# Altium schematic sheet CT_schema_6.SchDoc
size 278 x 170 mm
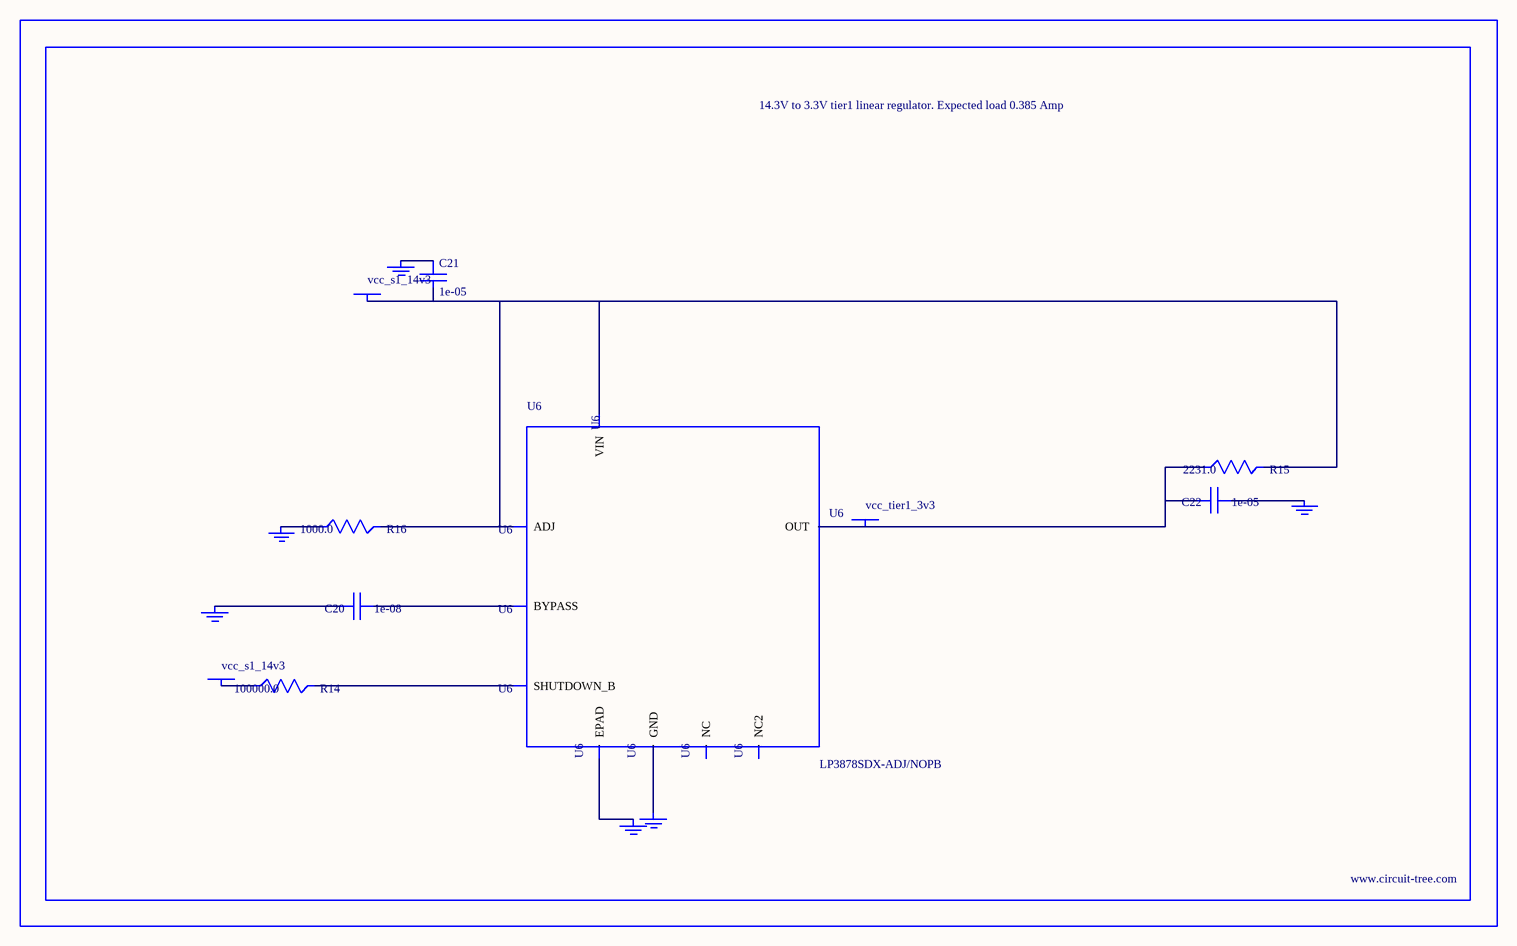
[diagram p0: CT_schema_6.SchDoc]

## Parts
BORDER5  (no value)
C20  1e-08  [C0402]
C21  1e-05  [C1210]
C22  1e-05  [C1210]
GND_INSTANCE_5_0  (no value)
GND_INSTANCE_5_1  (no value)
GND_INSTANCE_5_2  (no value)
GND_INSTANCE_5_3  (no value)
GND_INSTANCE_5_4  (no value)
GND_INSTANCE_5_5  (no value)
POWER_INSTANCE_5_0  vcc_s1_14v3
POWER_INSTANCE_5_1  vcc_s1_14v3
POWER_INSTANCE_5_2  vcc_tier1_3v3
R14  100000.0  [R0603]
R15  2231.0  [R0603]
R16  1000.0  [R0603]
U6  LP3878SDX-ADJ/NOPB  [WSON-8]

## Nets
NetC20_1: C20.1 U6.1(BYPASS)
NetC20_2: C20.2 GND_INSTANCE_5_0.0(GND)
NetC21_1: C21.1 GND_INSTANCE_5_1.0(GND)
NetC21_2: C21.2 POWER_INSTANCE_5_0.0(PWR) R15.2 R16.2 U6.4(VIN) U6.6(ADJ)
NetC22_1: C22.1 GND_INSTANCE_5_2.0(GND)
NetC22_2: C22.2 POWER_INSTANCE_5_2.0(PWR) R15.1 U6.5(OUT)
NetGND_INSTANCE_5_3_0: GND_INSTANCE_5_3.0(GND) R16.1
NetGND_INSTANCE_5_4_0: GND_INSTANCE_5_4.0(GND) U6.PAD(EPAD)
NetGND_INSTANCE_5_5_0: GND_INSTANCE_5_5.0(GND) U6.3(GND)
NetPOWER_INSTANCE_5_1_0: POWER_INSTANCE_5_1.0(PWR) R14.1
NetR14_2: R14.2 U6.8(SHUTDOWN_B)

Not connected (* = marked no-connect by the designer): U6 2(NC) 7(NC2)

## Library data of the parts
BORDER5 = BORDER_PAGE5
C20 = C0402C103K3RAC
C21 = C1210C106K5PACTU
C22 = GRM32DR61E106MA12L
GND_INSTANCE_5_0-GND_INSTANCE_5_5 = GND
POWER_INSTANCE_5_0-POWER_INSTANCE_5_2 = PWR
R14 = RC0603JR-07100KL
R15 = R15
R16 = RC0603JR-071KL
